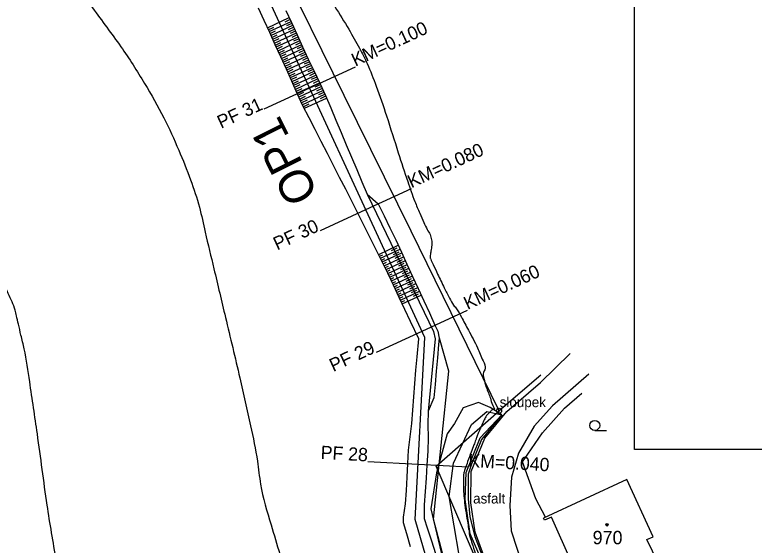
# Model space of a CAD drawing. Extents: x -478102 to -473059, y -1117705 to -1114104.
# Drawn here: x -476572 to -476461.5, y -1116810.6 to -1116731.4 of the extents above; entities that cross this region are included whole.
import ezdxf

# ---------------------------------------------------------------- set-up
doc = ezdxf.new("R2010")
doc.units = 0
for name, color, linetype in [('BodoveZnackySloupy', 7, 'Continuous'), ('Budovy', 7, 'Continuous'), ('HraniceSouvislehoPorostu', 7, 'Continuous'), ('LokalizacniPopisyPopisnaCisla', 7, 'Continuous'), ('ObPÚ', 7, 'Continuous'), ('Ploty', 7, 'Continuous'), ('POLYGONY_SITUACE_PF', 7, 'Continuous'), ('POLYGONY_SITUACE_PF_POPISY', 7, 'Continuous'), ('POLYGONY_SITUACE_PO', 7, 'Continuous'), ('PopisnaZnackaVyhybka', 7, 'Continuous'), ('PopisneZnackyKultura', 7, 'Continuous'), ('PopisObjektu', 7, 'Continuous'), ('PopisPovrchu', 7, 'Continuous'), ('ramecek', 7, 'Continuous'), ('RozhraniKultur', 7, 'Continuous'), ('RozhraniVozovky', 7, 'Continuous'), ('Teren_HranaSvahu', 7, 'Continuous'), ('Teren_PataSvahu', 7, 'Continuous'), ('TP_HS', 7, 'Continuous'), ('Vrstevnice_hlavni', 7, 'Continuous'), ('Vrstevnice_vedlejsi', 7, 'Continuous')]:
    doc.layers.add(name, color=color, linetype=linetype)

msp = doc.modelspace()

# ---------------------------------------------------------------- linework, layer by layer
for p, q in [((-476534.705, -1116732.235), (-476535.54, -1116730.418)), ((-476531.464, -1116730.739), (-476530.623, -1116732.553)), ((-476533.87, -1116734.052), (-476534.705, -1116732.235)), ((-476530.623, -1116732.553), (-476529.783, -1116734.368)), ((-476533.035, -1116735.87), (-476533.87, -1116734.052)), ((-476529.783, -1116734.368), (-476528.942, -1116736.183)), ((-476532.2, -1116737.687), (-476533.035, -1116735.87)), ((-476528.942, -1116736.183), (-476528.098, -1116737.996)), ((-476531.365, -1116739.504), (-476532.2, -1116737.687)), ((-476528.098, -1116737.996), (-476527.246, -1116739.806)), ((-476530.541, -1116741.327), (-476531.365, -1116739.504)), ((-476527.246, -1116739.806), (-476526.395, -1116741.616)), ((-476529.741, -1116743.161), (-476530.541, -1116741.327)), ((-476526.395, -1116741.616), (-476525.544, -1116743.426)), ((-476528.896, -1116744.973), (-476529.741, -1116743.161)), ((-476525.544, -1116743.426), (-476524.756, -1116745.265)), ((-476527.99, -1116746.758), (-476528.896, -1116744.973)), ((-476524.756, -1116745.265), (-476523.977, -1116747.108)), ((-476527.076, -1116748.539), (-476527.99, -1116746.758)), ((-476523.977, -1116747.108), (-476523.198, -1116748.951)), ((-476526.163, -1116750.32), (-476527.076, -1116748.539)), ((-476523.198, -1116748.951), (-476522.419, -1116750.794)), ((-476525.249, -1116752.101), (-476526.163, -1116750.32)), ((-476522.419, -1116750.794), (-476521.64, -1116752.638)), ((-476524.335, -1116753.882), (-476525.249, -1116752.101)), ((-476521.64, -1116752.638), (-476520.861, -1116754.481)), ((-476523.422, -1116755.663), (-476524.335, -1116753.882)), ((-476520.861, -1116754.481), (-476520.082, -1116756.324)), ((-476522.508, -1116757.444), (-476523.422, -1116755.663)), ((-476520.082, -1116756.324), (-476519.302, -1116758.166)), ((-476521.594, -1116759.225), (-476522.508, -1116757.444)), ((-476519.302, -1116758.166), (-476517.667, -1116759.615)), ((-476520.682, -1116761.007), (-476521.594, -1116759.225)), ((-476517.667, -1116759.615), (-476516.78, -1116761.408)), ((-476519.776, -1116762.791), (-476520.682, -1116761.007)), ((-476516.78, -1116761.408), (-476515.894, -1116763.202)), ((-476518.884, -1116764.582), (-476519.776, -1116762.791)), ((-476515.894, -1116763.202), (-476515.021, -1116765.002)), ((-476517.992, -1116766.373), (-476518.884, -1116764.582)), ((-476515.021, -1116765.002), (-476514.186, -1116766.819)), ((-476517.1, -1116768.165), (-476517.992, -1116766.373)), ((-476514.186, -1116766.819), (-476513.35, -1116768.636)), ((-476516.217, -1116769.96), (-476517.1, -1116768.165)), ((-476513.35, -1116768.636), (-476512.515, -1116770.453)), ((-476515.365, -1116771.769), (-476516.217, -1116769.96)), ((-476512.515, -1116770.453), (-476511.679, -1116772.27)), ((-476514.513, -1116773.578), (-476515.365, -1116771.769)), ((-476511.679, -1116772.27), (-476510.844, -1116774.087)), ((-476513.661, -1116775.388), (-476514.513, -1116773.578)), ((-476510.844, -1116774.087), (-476510.008, -1116775.904)), ((-476512.808, -1116777.197), (-476513.661, -1116775.388)), ((-476510.008, -1116775.904), (-476509.173, -1116777.722)), ((-476511.599, -1116779.764), (-476512.808, -1116777.197)), ((-476509.173, -1116777.722), (-476508.759, -1116778.621)), ((-476508.759, -1116778.621), (-476508.556, -1116779.691)), ((-476511.834, -1116782.456), (-476511.599, -1116779.764)), ((-476508.556, -1116779.691), (-476508.637, -1116780.629)), ((-476508.637, -1116780.629), (-476508.804, -1116782.622)), ((-476512.007, -1116784.45), (-476511.834, -1116782.456)), ((-476508.804, -1116782.622), (-476508.971, -1116784.616)), ((-476512.177, -1116786.444), (-476512.007, -1116784.45)), ((-476508.971, -1116784.616), (-476509.138, -1116786.61)), ((-476512.323, -1116788.439), (-476512.177, -1116786.444)), ((-476509.138, -1116786.61), (-476509.329, -1116788.603)), ((-476512.469, -1116790.434), (-476512.323, -1116788.439)), ((-476509.329, -1116788.603), (-476510.211, -1116790.557)), ((-476512.642, -1116792.427), (-476512.469, -1116790.434)), ((-476510.211, -1116790.557), (-476510.221, -1116792.56)), ((-476512.86, -1116794.418), (-476512.642, -1116792.427)), ((-476510.221, -1116792.56), (-476510.195, -1116794.564)), ((-476513.114, -1116796.407), (-476512.86, -1116794.418)), ((-476510.195, -1116794.564), (-476510.255, -1116796.564)), ((-476513.245, -1116798.403), (-476513.114, -1116796.407)), ((-476510.255, -1116796.564), (-476510.367, -1116798.561)), ((-476513.342, -1116800.401), (-476513.245, -1116798.403)), ((-476510.367, -1116798.561), (-476510.489, -1116800.557)), ((-476513.414, -1116802.4), (-476513.342, -1116800.401)), ((-476510.489, -1116800.557), (-476510.631, -1116802.552)), ((-476513.593, -1116804.393), (-476513.414, -1116802.4)), ((-476510.631, -1116802.552), (-476510.773, -1116804.548)), ((-476513.863, -1116806.381), (-476513.593, -1116804.393)), ((-476510.773, -1116804.548), (-476510.764, -1116806.596)), ((-476513.851, -1116807.251), (-476513.863, -1116806.381)), ((-476513.377, -1116808.907), (-476513.851, -1116807.251)), ((-476510.764, -1116806.596), (-476510.312, -1116808.011)), ((-476510.312, -1116808.011), (-476509.703, -1116809.917)), ((-476512.827, -1116810.83), (-476513.377, -1116808.907)), ((-476509.703, -1116809.917), (-476509.094, -1116811.822))]:
    msp.add_line(p, q)
for points in [[(-476534.212, -1116733.334), (-476530.933, -1116731.819)], [(-476530.8, -1116732.105), (-476531.62, -1116732.483)], [(-476534.079, -1116733.62), (-476533.26, -1116733.241)], [(-476533.947, -1116733.906), (-476530.668, -1116732.391)], [(-476533.683, -1116734.478), (-476530.404, -1116732.963)], [(-476530.536, -1116732.677), (-476531.356, -1116733.056)], [(-476530.272, -1116733.249), (-476531.091, -1116733.628)], [(-476533.815, -1116734.192), (-476532.995, -1116733.813)], [(-476533.55, -1116734.764), (-476532.731, -1116734.386)], [(-476533.418, -1116735.051), (-476530.139, -1116733.535)], [(-476533.154, -1116735.623), (-476529.875, -1116734.108)], [(-476530.007, -1116733.822), (-476530.827, -1116734.2)], [(-476529.743, -1116734.394), (-476530.562, -1116734.773)], [(-476533.286, -1116735.337), (-476532.466, -1116734.958)], [(-476533.022, -1116735.909), (-476532.202, -1116735.53)], [(-476532.889, -1116736.195), (-476529.61, -1116734.68)], [(-476532.625, -1116736.767), (-476529.346, -1116735.252)], [(-476529.478, -1116734.966), (-476530.298, -1116735.345)], [(-476529.214, -1116735.538), (-476530.033, -1116735.917)], [(-476532.757, -1116736.481), (-476531.937, -1116736.102)], [(-476532.493, -1116737.053), (-476531.673, -1116736.675)], [(-476532.36, -1116737.34), (-476529.082, -1116735.824)], [(-476532.096, -1116737.912), (-476528.817, -1116736.397)], [(-476528.949, -1116736.111), (-476529.769, -1116736.489)], [(-476528.685, -1116736.683), (-476529.505, -1116737.062)], [(-476532.228, -1116737.626), (-476531.408, -1116737.247)], [(-476531.964, -1116738.198), (-476531.144, -1116737.819)], [(-476531.832, -1116738.484), (-476528.553, -1116736.969)], [(-476531.567, -1116739.056), (-476528.288, -1116737.541)], [(-476528.42, -1116737.255), (-476529.24, -1116737.634)], [(-476528.156, -1116737.827), (-476528.976, -1116738.206)], [(-476531.699, -1116738.77), (-476530.88, -1116738.392)], [(-476531.435, -1116739.343), (-476530.615, -1116738.964)], [(-476531.303, -1116739.629), (-476528.024, -1116738.114)], [(-476531.038, -1116740.201), (-476527.759, -1116738.686)], [(-476527.892, -1116738.4), (-476528.711, -1116738.778)], [(-476527.627, -1116738.972), (-476528.447, -1116739.351)], [(-476531.17, -1116739.915), (-476530.351, -1116739.536)], [(-476530.774, -1116740.773), (-476527.495, -1116739.258)], [(-476530.509, -1116741.346), (-476527.23, -1116739.83)], [(-476527.363, -1116739.544), (-476528.182, -1116739.923)], [(-476530.906, -1116740.487), (-476530.086, -1116740.108)], [(-476530.641, -1116741.059), (-476529.822, -1116740.681)], [(-476530.245, -1116741.918), (-476526.966, -1116740.403)], [(-476529.98, -1116742.49), (-476526.702, -1116740.975)], [(-476527.098, -1116740.117), (-476527.918, -1116740.495)], [(-476526.834, -1116740.689), (-476527.653, -1116741.068)], [(-476530.377, -1116741.632), (-476529.557, -1116741.253)], [(-476530.113, -1116742.204), (-476529.293, -1116741.825)], [(-476529.716, -1116743.062), (-476526.437, -1116741.547)], [(-476529.451, -1116743.635), (-476526.173, -1116742.12)], [(-476526.569, -1116741.261), (-476527.389, -1116741.64)], [(-476526.305, -1116741.833), (-476527.125, -1116742.212)], [(-476529.848, -1116742.776), (-476529.028, -1116742.397)], [(-476529.584, -1116743.349), (-476528.764, -1116742.97)], [(-476529.187, -1116744.207), (-476525.908, -1116742.692)], [(-476528.923, -1116744.779), (-476525.644, -1116743.264)], [(-476526.04, -1116742.406), (-476526.86, -1116742.784)], [(-476525.776, -1116742.978), (-476526.596, -1116743.357)], [(-476529.319, -1116743.921), (-476528.5, -1116743.542)], [(-476529.055, -1116744.493), (-476528.235, -1116744.114)], [(-476528.658, -1116745.351), (-476525.379, -1116743.836)], [(-476525.512, -1116743.55), (-476526.331, -1116743.929)], [(-476528.79, -1116745.065), (-476527.971, -1116744.687)], [(-476519.302, -1116758.166), (-476509.376, -1116778.673), (-476509.133, -1116779.786), (-476510.211, -1116790.557)], [(-476517.579, -1116767.158), (-476514.652, -1116765.805)], [(-476517.315, -1116767.73), (-476514.389, -1116766.378)], [(-476514.858, -1116766.253), (-476515.708, -1116766.646)], [(-476517.447, -1116767.444), (-476516.942, -1116767.21)], [(-476517.036, -1116768.296), (-476514.125, -1116766.951)], [(-476516.757, -1116768.861), (-476513.862, -1116767.523)], [(-476514.594, -1116766.826), (-476515.436, -1116767.215)], [(-476514.33, -1116767.398), (-476515.163, -1116767.784)], [(-476517.183, -1116768.016), (-476516.669, -1116767.779)], [(-476516.897, -1116768.579), (-476516.397, -1116768.348)], [(-476516.479, -1116769.427), (-476513.598, -1116768.096)], [(-476516.201, -1116769.993), (-476513.335, -1116768.669)], [(-476514.066, -1116767.971), (-476514.891, -1116768.352)], [(-476513.802, -1116768.543), (-476514.618, -1116768.921)], [(-476516.618, -1116769.144), (-476516.124, -1116768.916)], [(-476516.34, -1116769.71), (-476515.852, -1116769.485)], [(-476515.933, -1116770.564), (-476513.072, -1116769.242)], [(-476515.664, -1116771.134), (-476512.808, -1116769.815)], [(-476513.538, -1116769.116), (-476514.346, -1116769.489)], [(-476513.274, -1116769.688), (-476514.074, -1116770.058)], [(-476516.067, -1116770.279), (-476515.58, -1116770.053)], [(-476515.798, -1116770.849), (-476515.307, -1116770.622)], [(-476515.395, -1116771.704), (-476512.545, -1116770.387)], [(-476515.127, -1116772.275), (-476512.282, -1116770.96)], [(-476513.01, -1116770.261), (-476513.801, -1116770.627)], [(-476512.746, -1116770.833), (-476513.529, -1116771.195)], [(-476515.53, -1116771.419), (-476515.035, -1116771.19)], [(-476515.261, -1116771.99), (-476514.762, -1116771.759)], [(-476514.858, -1116772.845), (-476512.018, -1116771.533)], [(-476514.59, -1116773.416), (-476511.755, -1116772.106)], [(-476512.482, -1116771.406), (-476513.256, -1116771.764)], [(-476512.218, -1116771.978), (-476512.984, -1116772.332)], [(-476514.992, -1116772.56), (-476514.49, -1116772.328)], [(-476514.724, -1116773.13), (-476514.217, -1116772.896)], [(-476514.321, -1116773.986), (-476511.491, -1116772.678)], [(-476511.954, -1116772.551), (-476512.711, -1116772.901)], [(-476511.69, -1116773.123), (-476512.439, -1116773.469)], [(-476514.455, -1116773.701), (-476513.945, -1116773.465)], [(-476514.187, -1116774.271), (-476513.672, -1116774.033)], [(-476514.053, -1116774.556), (-476511.228, -1116773.251)]]:
    msp.add_lwpolyline(points)
at = {"layer": 'BodoveZnackySloupy'}
for radius in [0.375, 0.05]:
    msp.add_circle((-476499.58, -1116790.5), radius, dxfattribs=at)
at = {"layer": 'Budovy'}
for p, q in [((-476480.507, -1116800.783), (-476492.94, -1116806.52)), ((-476476.546, -1116809.326), (-476480.507, -1116800.783)), ((-476491.78, -1116806.38), (-476492.81, -1116806.83)), ((-476478.1, -1116836.8), (-476491.78, -1116806.38)), ((-476492.81, -1116806.83), (-476492.94, -1116806.52)), ((-476477.506, -1116809.723), (-476476.546, -1116809.326)), ((-476471.43, -1116822.291), (-476477.506, -1116809.723))]:
    msp.add_line(p, q, dxfattribs=at)
at = {"layer": 'HraniceSouvislehoPorostu'}
msp.add_lwpolyline([(-476503.667, -1116823.297), (-476501.663, -1116823.142), (-476501.269, -1116822.977), (-476499.06, -1116820.987), (-476501.643, -1116814.144), (-476503.911, -1116808.879), (-476504.635, -1116803.762), (-476504.524, -1116799.738), (-476502.429, -1116794.533), (-476499.158, -1116791.112), (-476500.941, -1116790.007), (-476502.678, -1116789.287), (-476504.94, -1116790.065), (-476506.236, -1116792.421), (-476507.371, -1116793.97), (-476508.92, -1116799.781), (-476509.8, -1116805.165), (-476507.792, -1116813.551)], close=True, dxfattribs=at)
at = {"layer": 'ObPÚ'}
msp.add_lwpolyline([(-476490.13, -1116842.91), (-476508.98, -1116798.77), (-476499.58, -1116790.5), (-476512.73, -1116763.68), (-476522.74, -1116743.44), (-476532.64, -1116723.27), (-476537.9, -1116712.49), (-476599.28, -1116718.82), (-476629.49, -1116719.44), (-476650.74, -1116720.15), (-476671.65, -1116720.77), (-476692.89, -1116721.55)], dxfattribs=at)
at = {"layer": 'Ploty'}
msp.add_line((-476493.362, -1116785.193), (-476499.58, -1116790.5), dxfattribs=at)
msp.add_lwpolyline([(-476492.676, -1116806.398), (-476494.1, -1116803.644), (-476496.089, -1116798.145), (-476495.288, -1116796.97), (-476493.089, -1116793.815), (-476489.802, -1116790.11), (-476487.243, -1116787.893)], dxfattribs=at)
at = {"layer": 'POLYGONY_SITUACE_PF'}
for points in [[(-476534.681, -1116745.441), (-476527.872, -1116742.298), (-476521.063, -1116739.154)], [(-476526.298, -1116763.599), (-476519.489, -1116760.456), (-476512.679, -1116757.312)], [(-476517.915, -1116781.758), (-476511.105, -1116778.614), (-476504.296, -1116775.47)], [(-476519.186, -1116798.078), (-476511.697, -1116798.488), (-476504.208, -1116798.898)]]:
    msp.add_lwpolyline(points, dxfattribs=at)
at = {"layer": 'POLYGONY_SITUACE_PO'}
msp.add_lwpolyline([(-476503.246, -1116837.201), (-476512.149, -1116806.742), (-476510.661, -1116779.576), (-476536.613, -1116723.365), (-476541.714, -1116718.348), (-476546.146, -1116716.759)], dxfattribs=at)
at = {"layer": 'PopisnaZnackaVyhybka'}
for radius in [0.18, 0.0797]:
    msp.add_circle((-476483.459, -1116807.534), radius, dxfattribs=at)
at = {"layer": 'PopisneZnackyKultura'}
msp.add_line((-476485.298, -1116793.441), (-476483.538, -1116793.441), dxfattribs=at)
msp.add_circle((-476485.298, -1116792.701), 0.75, dxfattribs=at)
at = {"layer": 'ramecek'}
msp.add_lwpolyline([(-476479.335, -1116586.282), (-476182.335, -1116586.282), (-476182.335, -1116796.282), (-476479.335, -1116796.282)], close=True, dxfattribs=at)
at = {"layer": 'RozhraniKultur'}
msp.add_line((-476507.1, -1116784.61), (-476508.472, -1116779.674), dxfattribs=at)
msp.add_lwpolyline([(-476490.21, -1116852.89), (-476505.97, -1116819.69), (-476509.41, -1116806.69), (-476507.1, -1116784.61)], dxfattribs=at)
at = {"layer": 'RozhraniVozovky'}
for points in [[(-476490.349, -1116825.506), (-476486.291, -1116834.14), (-476483.076, -1116841.048), (-476483.085, -1116841.925), (-476483.97, -1116842.691), (-476486.077, -1116843.648), (-476487.217, -1116843.934), (-476487.93, -1116843.214), (-476491.436, -1116836.397), (-476497.994, -1116822.204), (-476502.044, -1116811.617), (-476503.151, -1116808.629), (-476503.828, -1116804.26), (-476503.771, -1116799.56), (-476501.723, -1116794.622), (-476498.437, -1116790.602), (-476493.387, -1116786.282), (-476488.978, -1116781.97)], [(-476486.198, -1116785.025), (-476491.618, -1116789.798), (-476494.363, -1116792.808), (-476496.677, -1116796.826), (-476497.718, -1116800.431), (-476497.972, -1116804.656), (-476497.798, -1116808.431), (-476496.057, -1116813.746), (-476494.884, -1116816.479), (-476494.577, -1116816.424), (-476490.349, -1116825.506)]]:
    msp.add_lwpolyline(points, dxfattribs=at)
at = {"layer": 'Teren_HranaSvahu'}
msp.add_lwpolyline([(-476496.01, -1116833.929), (-476499.708, -1116826.401), (-476501.648, -1116822.147), (-476505.565, -1116812.08), (-476507.025, -1116803.334), (-476506.405, -1116798.313), (-476503.711, -1116792.546), (-476501.404, -1116790.625), (-476499.158, -1116791.112)], dxfattribs=at)
at = {"layer": 'Teren_PataSvahu'}
msp.add_lwpolyline([(-476499.158, -1116791.112), (-476502.208, -1116794.823), (-476503.708, -1116798.478), (-476504.196, -1116799.961), (-476504.191, -1116803.667), (-476503.982, -1116806.345), (-476503.215, -1116809.287), (-476501.38, -1116814.102), (-476499.454, -1116819.846), (-476497.667, -1116824.545), (-476496.291, -1116827.707), (-476491.983, -1116837.253)], dxfattribs=at)
at = {"layer": 'Vrstevnice_hlavni'}
msp.add_spline([(-476527.602, -1116721.186), (-476528.714, -1116721.886), (-476528.23, -1116723.439), (-476526.707, -1116726.197), (-476524.145, -1116730.158), (-476522.056, -1116733.559), (-476520.442, -1116736.398), (-476519.302, -1116738.677), (-476517.957, -1116742.038), (-476516.407, -1116746.483), (-476514.652, -1116752.01), (-476513.242, -1116756.272), (-476512.175, -1116759.27), (-476511.452, -1116761.003), (-476510.834, -1116762.401), (-476510.32, -1116763.464), (-476509.911, -1116764.191), (-476509.686, -1116764.969), (-476509.645, -1116765.797), (-476509.788, -1116766.676), (-476509.864, -1116767.316), (-476509.873, -1116767.717), (-476509.813, -1116767.879), (-476509.447, -1116768.672), (-476508.772, -1116770.097), (-476507.79, -1116772.153), (-476506.994, -1116773.702), (-476506.384, -1116774.742), (-476505.959, -1116775.275), (-476505.223, -1116776.514), (-476504.175, -1116778.459), (-476502.816, -1116781.111), (-476501.986, -1116783.05), (-476501.687, -1116784.275), (-476501.918, -1116784.786), (-476501.862, -1116785.683), (-476501.521, -1116786.966), (-476500.892, -1116788.635), (-476500.503, -1116789.743), (-476500.351, -1116790.291), (-476500.437, -1116790.278), (-476500.545, -1116790.32), (-476500.674, -1116790.416), (-476500.825, -1116790.567), (-476500.993, -1116790.734), (-476501.178, -1116790.917), (-476501.381, -1116791.115), (-476501.65, -1116791.544), (-476501.983, -1116792.205), (-476502.382, -1116793.096), (-476502.697, -1116793.835), (-476502.928, -1116794.421), (-476503.075, -1116794.854), (-476503.351, -1116795.612), (-476503.755, -1116796.696), (-476504.288, -1116798.104), (-476504.653, -1116799.131), (-476504.852, -1116799.775), (-476504.883, -1116800.036), (-476504.898, -1116800.591), (-476504.898, -1116801.439), (-476504.883, -1116802.579), (-476504.782, -1116803.886), (-476504.595, -1116805.358), (-476504.322, -1116806.996), (-476504.138, -1116808.141), (-476504.043, -1116808.793), (-476504.038, -1116808.953), (-476503.866, -1116809.567), (-476503.528, -1116810.636), (-476503.024, -1116812.159), (-476502.59, -1116813.421), (-476502.228, -1116814.421), (-476501.936, -1116815.159), (-476501.534, -1116816.252), (-476501.021, -1116817.7), (-476500.398, -1116819.504), (-476499.972, -1116820.733), (-476499.743, -1116821.386), (-476499.711, -1116821.465), (-476499.591, -1116821.797), (-476499.382, -1116822.382), (-476499.086, -1116823.219), (-476498.839, -1116823.9), (-476498.641, -1116824.424), (-476498.491, -1116824.791), (-476498.274, -1116825.277), (-476497.99, -1116825.882), (-476497.637, -1116826.604), (-476497.279, -1116827.424), (-476496.914, -1116828.341), (-476496.542, -1116829.355), (-476496.028, -1116830.632), (-476495.371, -1116832.172), (-476494.572, -1116833.974), (-476494.02, -1116835.509), (-476493.715, -1116836.779)], degree=3, dxfattribs=at)
at = {"layer": 'Vrstevnice_vedlejsi'}
for points in [[(-476563.268, -1116822.388), (-476564.458, -1116818.802), (-476565.742, -1116812.867), (-476567.118, -1116804.582), (-476568.587, -1116793.948), (-476569.729, -1116786.177), (-476570.545, -1116781.268), (-476571.033, -1116779.221), (-476571.424, -1116777.575), (-476571.719, -1116776.332), (-476571.916, -1116775.49), (-476572.924, -1116773.024), (-476574.742, -1116768.935), (-476577.371, -1116763.222), (-476579.69, -1116758.036), (-476581.698, -1116753.375), (-476583.396, -1116749.241), (-476584.874, -1116745.101), (-476586.132, -1116740.955), (-476587.171, -1116736.803), (-476588.314, -1116732.57), (-476589.562, -1116728.255), (-476590.916, -1116723.859), (-476591.963, -1116720.904), (-476592.704, -1116719.39), (-476593.139, -1116719.317), (-476593.281, -1116719.095), (-476593.129, -1116718.723), (-476592.685, -1116718.202), (-476592.314, -1116717.782), (-476592.016, -1116717.465), (-476591.792, -1116717.249), (-476591.819, -1116716.919), (-476592.098, -1116716.475), (-476592.629, -1116715.916), (-476593.304, -1116715.194), (-476594.125, -1116714.306), (-476595.09, -1116713.255), (-476595.604, -1116712.296), (-476595.666, -1116711.43), (-476595.276, -1116710.657), (-476595.579, -1116709.15), (-476596.575, -1116706.91), (-476598.265, -1116703.935), (-476599.415, -1116701.891), (-476600.025, -1116700.778), (-476600.096, -1116700.595), (-476600.16, -1116700.443), (-476600.218, -1116700.322), (-476600.269, -1116700.232), (-476600.331, -1116700.125), (-476600.402, -1116700.001), (-476600.484, -1116699.86), (-476600.74, -1116699.49)], [(-476571.958, -1116704.162), (-476571.904, -1116704.215), (-476571.688, -1116704.429), (-476571.311, -1116704.803), (-476570.773, -1116705.338), (-476569.946, -1116706.363), (-476568.83, -1116707.879), (-476567.427, -1116709.886), (-476566.203, -1116711.628), (-476565.16, -1116713.105), (-476564.298, -1116714.317), (-476563.772, -1116715.225), (-476563.581, -1116715.829), (-476563.726, -1116716.129), (-476564.073, -1116716.669), (-476564.621, -1116717.45), (-476565.371, -1116718.471), (-476565.697, -1116719.715), (-476565.599, -1116721.18), (-476565.077, -1116722.867), (-476563.322, -1116725.926), (-476560.334, -1116730.356), (-476556.114, -1116736.158), (-476552.562, -1116741.631), (-476549.677, -1116746.776), (-476547.46, -1116751.593), (-476545.693, -1116756.042), (-476544.374, -1116760.122), (-476543.504, -1116763.833), (-476542.206, -1116769.314), (-476540.482, -1116776.566), (-476538.329, -1116785.587), (-476536.736, -1116792.746), (-476535.702, -1116798.044), (-476535.228, -1116801.481), (-476533.66, -1116807.541), (-476530.999, -1116816.224), (-476527.246, -1116827.53), (-476524.726, -1116835.32), (-476523.44, -1116839.595), (-476523.389, -1116840.354), (-476523.331, -1116841.083), (-476523.266, -1116841.783), (-476523.195, -1116842.453), (-476522.8, -1116844.094), (-476522.082, -1116846.705), (-476521.041, -1116850.288), (-476519.77, -1116855.097), (-476518.27, -1116861.134), (-476516.539, -1116868.399), (-476515.387, -1116873.283), (-476514.813, -1116875.785), (-476514.818, -1116875.907), (-476514.695, -1116876.43), (-476514.444, -1116877.353), (-476514.064, -1116878.676), (-476513.598, -1116880.016), (-476513.045, -1116881.373), (-476512.404, -1116882.746), (-476510.965, -1116886.684), (-476508.726, -1116893.188), (-476505.69, -1116902.257), (-476503.32, -1116909.062), (-476501.617, -1116913.604), (-476500.581, -1116915.881), (-476499.982, -1116918.695), (-476499.82, -1116922.044), (-476500.095, -1116925.93), (-476500.622, -1116930.955), (-476501.399, -1116937.119), (-476502.428, -1116944.424), (-476503.284, -1116951.043), (-476503.968, -1116956.977), (-476504.479, -1116962.226), (-476505.481, -1116968.833), (-476506.974, -1116976.798), (-476508.959, -1116986.121), (-476510.49, -1116993.241), (-476511.568, -1116998.159), (-476512.192, -1117000.873), (-476513.406, -1117005.693), (-476515.21, -1117012.619), (-476517.605, -1117021.651), (-476519.543, -1117028.708), (-476521.025, -1117033.789), (-476522.05, -1117036.895), (-476522.813, -1117039.387), (-476523.316, -1117041.266), (-476523.557, -1117042.532), (-476525.061, -1117047.398), (-476527.83, -1117055.865), (-476531.861, -1117067.933), (-476534.429, -1117077.623), (-476535.532, -1117084.937), (-476535.172, -1117089.874), (-476535.368, -1117095.964), (-476536.121, -1117103.207)]]:
    msp.add_spline(points, degree=3, dxfattribs=at)

# ---------------------------------------------------------------- texts
at = {"layer": 'LokalizacniPopisyPopisnaCisla'}
msp.add_text('970', height=2, dxfattribs=at).set_placement((-476485.61, -1116810.44))
at = {"layer": 'POLYGONY_SITUACE_PF_POPISY'}
for s, rotation, p in [('KM=0.100', 24.78206, (-476521.074, -1116739.159)), ('PF 31', 24.78206, (-476541.141, -1116748.424)), ('KM=0.080', 24.78206, (-476512.691, -1116757.317)), ('PF 30', 24.78206, (-476532.758, -1116766.582)), ('KM=0.060', 24.78206, (-476504.307, -1116775.475)), ('PF 29', 24.78206, (-476524.375, -1116784.74)), ('PF 28', 356.86492, (-476526.291, -1116797.689)), ('KM=0.040', 356.86492, (-476504.221, -1116798.897))]:
    msp.add_text(s, height=1.9765, rotation=rotation, dxfattribs=at).set_placement(p)
at = {"layer": 'PopisObjektu'}
msp.add_text('sloupek', height=1.5, dxfattribs=at).set_placement((-476499.503, -1116789.972))
at = {"layer": 'PopisPovrchu'}
msp.add_text('asfalt', height=1.5, dxfattribs=at).set_placement((-476503.469, -1116804.354))
at = {"layer": 'TP_HS'}
msp.add_text('OP1', height=5, rotation=116.60575, dxfattribs=at).set_placement((-476526.519, -1116758.205))

doc.saveas('drawing.dxf')
